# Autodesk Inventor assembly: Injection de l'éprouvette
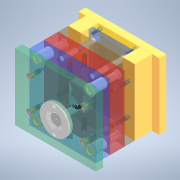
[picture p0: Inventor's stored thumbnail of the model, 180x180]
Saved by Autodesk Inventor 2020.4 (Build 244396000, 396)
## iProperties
Created: 2021-10
Part Number: Injection de l'éprouvette
Document SubType Name: Assembly
Designer: mel
Author: mel
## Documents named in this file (6)
- D:\travail\année 2020-2021\itec\prépa injection plastique eduscol\dossier de travail\Ensemble des pièces de l'activité\Conception de moule1\Injection de l'éprouvette.iam
- D:\travail\année 2020-2021\itec\prépa injection plastique eduscol\dossier de travail\Ensemble des pièces de l'activité\Conception de moule1\Injection de l'éprouvette_éprouvette_LY.iam
- D:\travail\année 2020-2021\itec\prépa injection plastique eduscol\dossier de travail\Ensemble des pièces de l'activité\Conception de moule1\Injection de l'éprouvette_RG.ipt
- D:\travail\année 2020-2021\itec\prépa injection plastique eduscol\dossier de travail\Ensemble des pièces de l'activité\Conception de moule1\Bague de centrage\LKM_LR\Injection de l'éprouvette_LR-100-36.ipt
- D:\travail\année 2020-2021\itec\prépa injection plastique eduscol\dossier de travail\Ensemble des pièces de l'activité\Conception de moule1\Mo\FUTABA_SA-S 3\Injection de l'éprouvette_MB.iam
- D:\travail\année 2020-2021\itec\prépa injection plastique eduscol\dossier de travail\Ensemble des pièces de l'activité\Conception de moule1\Buse d'injection\HASCO_Z51\Injection de l'éprouvette_Z51-18x56-3,5_1.ipt
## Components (5 placed, 5 different names)
1. Injection de l'éprouvette_éprouvette_LY:1 [sub-assembly] — Affleurement:1, Affleurement:2, Affleurement:3, Affleurement:10, Affleurement:11
2. Injection de l'éprouvette_RG:1 — Affleurement:4, Affleurement:5, Affleurement:6, Affleurement:8, Placage:3
3. Injection de l'éprouvette_MB:1 [sub-assembly] — Affleurement:11, Placage:1, Angle:1, Placage:2, Placage:4
4. Injection de l'éprouvette_Z51-18x56-3,5_1:1 — Placage:2, Placage:3, Placage:5
5. Injection de l'éprouvette_LR-100-36:1 — Placage:4, Placage:5
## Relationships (15: Flush 9, Mate 5, Angle 1)
- Affleurement:1 [Flush]: Injection de l'éprouvette_éprouvette_LY:1
- Affleurement:2 [Flush]: Injection de l'éprouvette_éprouvette_LY:1
- Affleurement:3 [Flush]: Injection de l'éprouvette_éprouvette_LY:1
- Affleurement:4 [Flush]: Injection de l'éprouvette_RG:1
- Affleurement:5 [Flush]: Injection de l'éprouvette_RG:1
- Affleurement:6 [Flush]: Injection de l'éprouvette_RG:1
- Affleurement:8 [Flush]: Injection de l'éprouvette_RG:1
- Affleurement:10 [Flush]: Injection de l'éprouvette_éprouvette_LY:1
- Affleurement:11 [Flush]: Injection de l'éprouvette_éprouvette_LY:1 ↔ Injection de l'éprouvette_MB:1
- Placage:1 [Mate]: Injection de l'éprouvette_MB:1
- Angle:1: Injection de l'éprouvette_MB:1
- Placage:2 [Mate]: Injection de l'éprouvette_MB:1 ↔ Injection de l'éprouvette_Z51-18x56-3,5_1:1
- Placage:3 [Mate]: Injection de l'éprouvette_RG:1 ↔ Injection de l'éprouvette_Z51-18x56-3,5_1:1
- Placage:4 [Mate]: Injection de l'éprouvette_MB:1 ↔ Injection de l'éprouvette_LR-100-36:1
- Placage:5 [Mate]: Injection de l'éprouvette_Z51-18x56-3,5_1:1 ↔ Injection de l'éprouvette_LR-100-36:1
